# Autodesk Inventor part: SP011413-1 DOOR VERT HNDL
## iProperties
Company: MiniTec Framing Systems, LLC
Created: 2013-01
Part Number: SP011413-1 DOOR VERT HNDL
Material: Aluminum-6061
Description: PROFILE 19X45
Document SubType Name: Modeling
Designer: Administrator
Stock Number: 20.1001 PROFILE 19X45
Density: 2.71 g/cm^3
Mass: 1294.64 g
Surface Area: 2591.87 cm^2
Volume: 477.727 cm^3
FINISH: CLEAR ANODIZED
Author: Administrator
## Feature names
1. Extrusion1
2. Hole1
